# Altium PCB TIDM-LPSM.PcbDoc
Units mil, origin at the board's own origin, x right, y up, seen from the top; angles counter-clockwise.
Board outline 2400 x 1200 mil, 2 copper layers (Top Layer, Bottom Layer), stack 62 mil thick; 16 components, 20 nets, 69 pads, 30 vias.
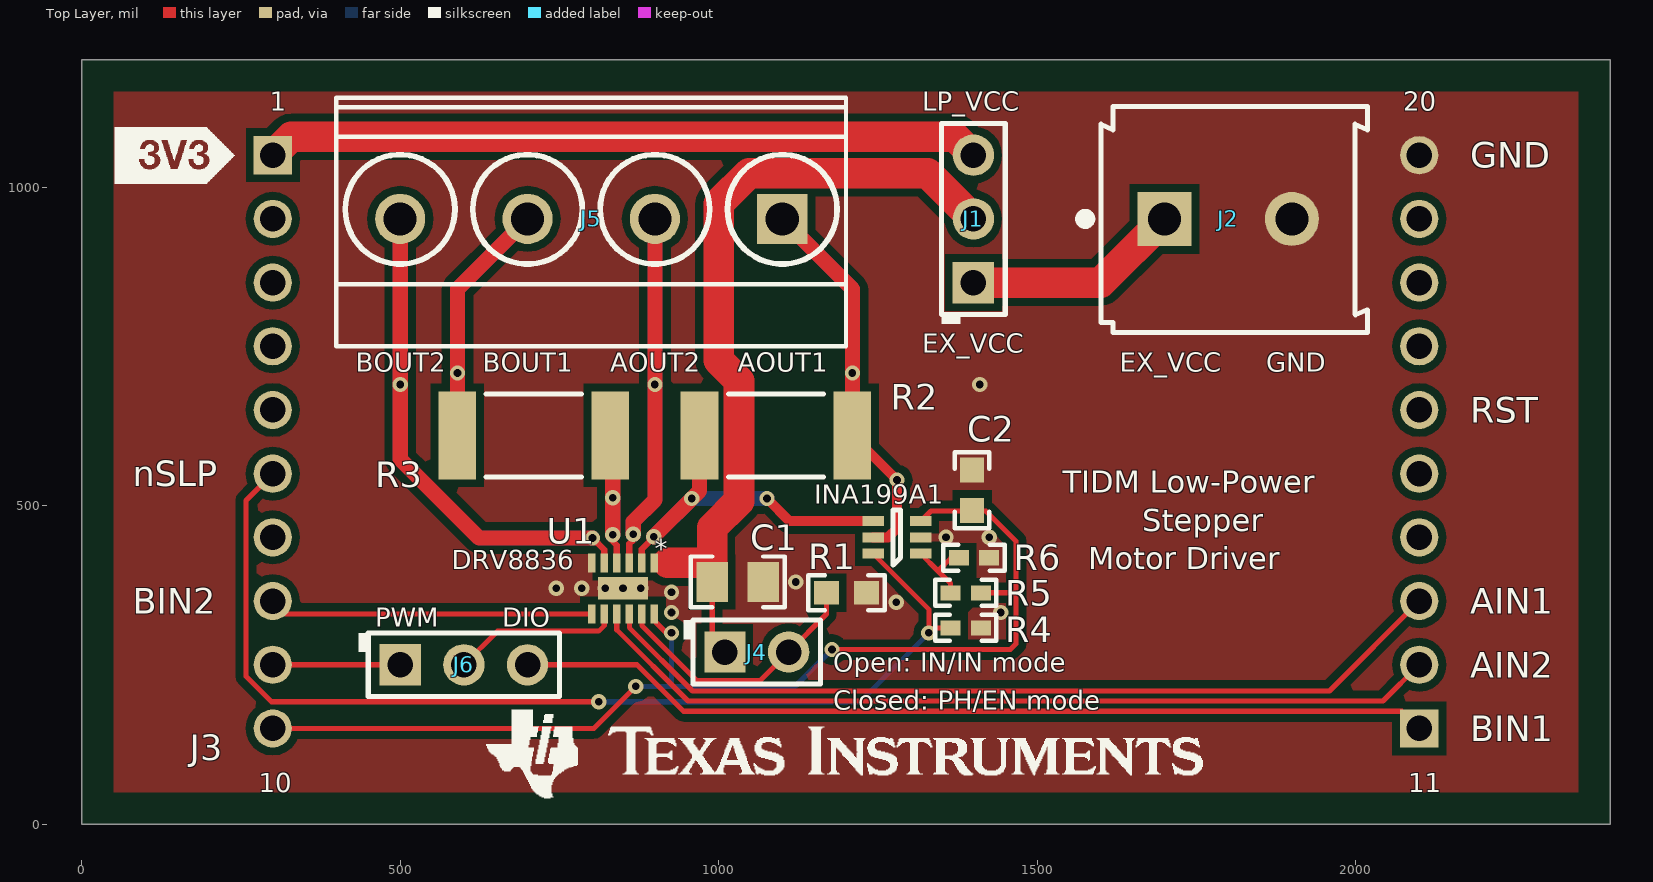
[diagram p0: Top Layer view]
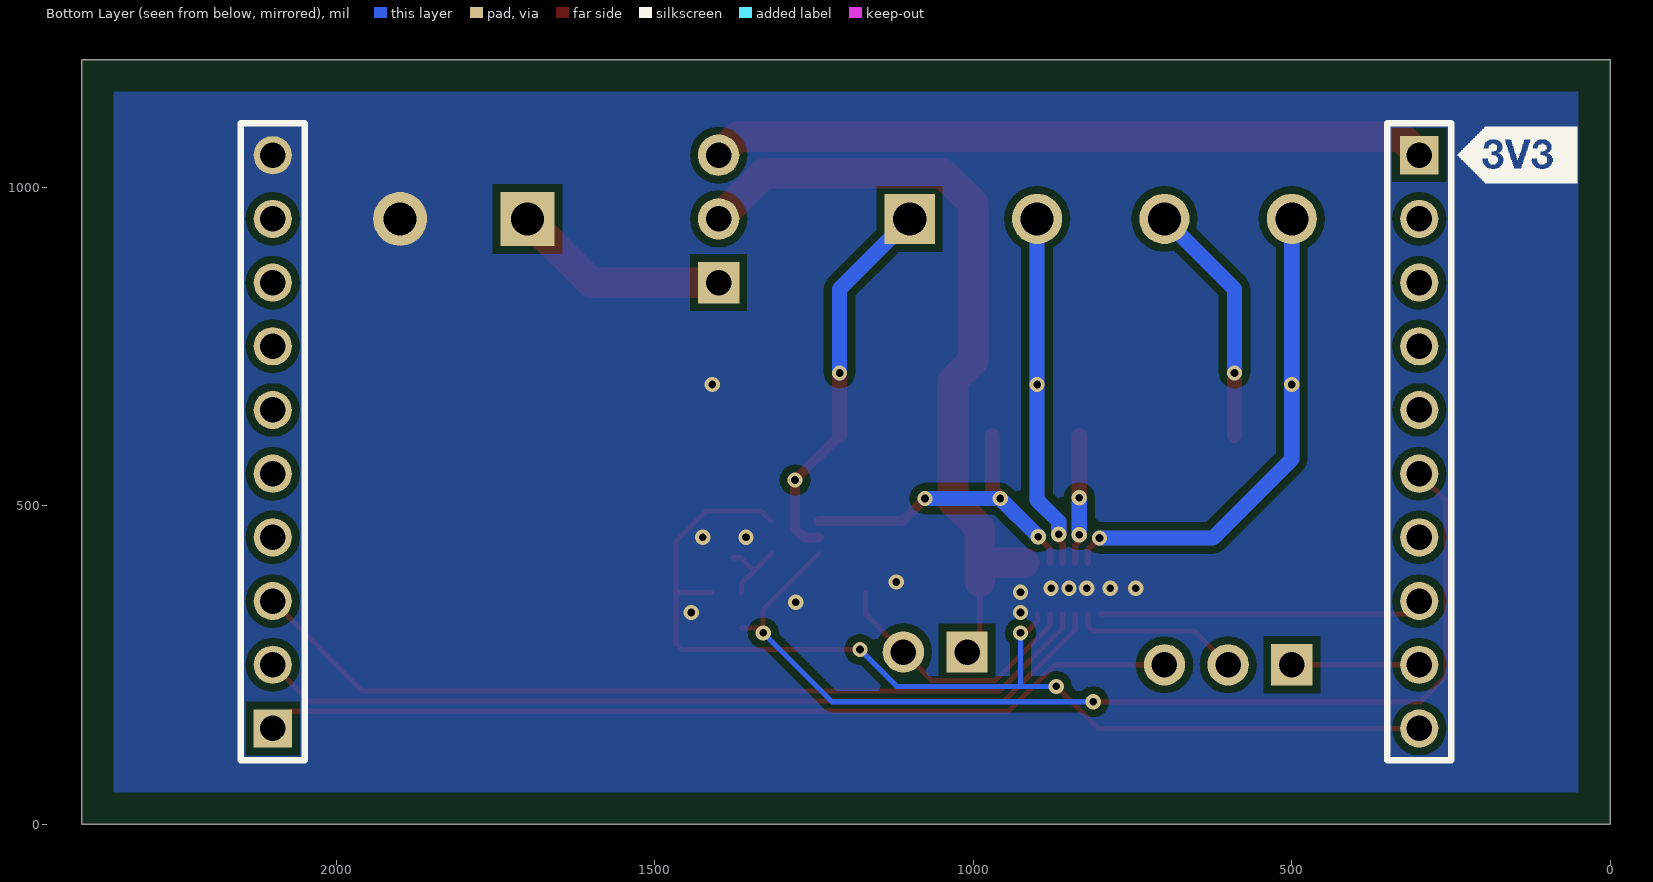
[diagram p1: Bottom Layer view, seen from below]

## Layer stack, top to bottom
Top Layer: signal copper 1.4
Dielectric: core 59.2, FR-4, Dk 4.8
Bottom Layer: signal copper 1.4

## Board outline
0,0 2400,0 2400,1200 0,1200

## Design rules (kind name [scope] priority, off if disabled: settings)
AcuteAngle [All] p1: minimum=4.50000000000000E+0001 checktracksonly=FALSE
AssemblyTestPointUsage [All] p1: valid=2
Clearance Clearance_DRV [InComponent('U1') vs InComponent('U1')] p1: gap=7.5
Clearance Clearance_BoardEdge_MountingHoles [OnCopper and InComponentClass('Mounting Holes') vs IsKeepOut] p2: gap=40
Clearance Clearance_BoardEdge_Poly [OnCopper and InPoly vs IsKeepOut] p3: gap=25
Clearance Clearance_BoardEdge [OnCopper and Not InComponentClass('Logo') and not InComponentClass('FiducialMark') and not InRegion(1000,500,4000,800) and Not IsKeepout vs IsKeepOut] p4: gap=75
Clearance Clearance_Poly [InPolygon] p5: gap=12
Clearance [All] p6: gap=8
ComponentClearance [All] p1: gap=25 collisioncheckmode=3 verticalgap=10 showdistances=FALSE
DiffPairsRouting [All] p1: maxlimit=100 minlimit=10 mostfreqgap=10 maxuncoupledlength=1000
FabricationTestPointUsage TestPointUsage [All] p1: valid=2 allowmultiple=FALSE
FabricationTestpoint Testpoint [All] p1: side=3 testpointundercomponent=TRUE minsize=40 maxsize=100 preferedsize=60 minholesize=0 maxholesize=40 preferedholesize=32 testpointgrid=1 allowsidetop=TRUE allowsidebottom=TRUE usegrid=TRUE gridtolerance=0.01
FanoutControl Fanout_LCC [IsLCC] p1: bgadir=Out bgaviamode=Centered fanoutstyle=Auto fanoutdirection=Alternating viagrid=1 // Fanout_LCC (Default Rule)
FanoutControl Fanout_BGA [IsBGA] p2: bgadir=Out bgaviamode=Centered fanoutstyle=Auto fanoutdirection=Alternating viagrid=1 // Fanout_BGA (Default Rule)
FanoutControl Fanout_Default [All] p4: bgadir=Out bgaviamode=Centered fanoutstyle=Auto fanoutdirection=Alternating viagrid=1 // Fanout_Default (Default Rule)
FanoutControl Fanout_Small [(CompPinCount < 5)] p5: bgadir=Out bgaviamode=Centered fanoutstyle=Auto fanoutdirection=OutThenIn viagrid=1 // Fanout_Small (Default Rule)
HoleSize [All] p1: absolutevalues=TRUE maxlimit=251 minlimit=8 maxpercent=80.000 minpercent=20.000
MinimumAnnularRing MinimumAnnularRing_ThermalPadVias [IsVia and InAnyComponent] p1: minimumring=5.91
MinimumAnnularRing [All] p2: minimumring=9
MinimumSolderMaskSliver MinimumSolderMaskSliver_Logo [InComponentClass('Logo') vs InComponentClass('Logo')] p1: minsoldermaskwidth=0.7
MinimumSolderMaskSliver [All] p2: minsoldermaskwidth=3.94
PlaneConnect [All] p1: planeconnectstyle=Relief reliefexpansion=10 reliefentries=4 reliefconductorwidth=10 reliefairgap=10
PolygonConnect [All] p1: connectstyle=Direct reliefconductorwidth=10 reliefentries=4 polygonreliefangle="90 Angle" airgapwidth=10
RoutingVias ThermalPadVias [IsVia and InAnyComponent] p1: holewidth=7.87 width=19.68 viastyle="Through Hole" minholewidth=7.87 minwidth=19.68 maxholewidth=12.99 maxwidth=23.62
RoutingVias [All] p2: holewidth=16 width=34 viastyle="Through Hole" minholewidth=7.87 minwidth=26 maxholewidth=40 maxwidth=65
SMDToCorner [All] p1: distance=30000
SilkToSilkClearance [All] p1: silktosilkclearance=5
SilkscreenOverComponentPads [All] p1: minsilkscreentomaskgap=5
SolderMaskExpansion [All] p1: expansion=1.97
Width [All] p1: maxlimit=100 minlimit=6 preferedwidth=10 checkconnectedcopper=TRUE
14 further rules are at their usual default settings.

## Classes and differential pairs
component class Header: J1 J4 J6

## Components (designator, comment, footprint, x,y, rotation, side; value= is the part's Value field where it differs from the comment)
C1 "C0805C106K9PAC" 0805_HV 1030,380 r0 top
C2 "0603YC104JAT2A" 0603 1398,524 r90 top
INA199A1 "INA199A1DCK" DCK0006A_N 1280,450 r180 top (schematic designator U2)
J1 "5-146278-3" TE_5-146278-3 1400,950 r90 top
J2 "282841-2" TEC_282841-2 1800,950 r0 top
J3 "Used in BOM report" SSW-110-23-F-S 300,1050 r0 top
J4 "5-146278-2" TE_5-146278-2 1060,270 r0 top
J5 "39544-3004" MOLEX_39544-3004 800,950 r180 top
J6 "5-146278-3" TE_5-146278-3 600,250 r0 top
R1 "CRCW060320K0JNEA" 0603 1201,363 r180 top
R2 "CRA2512-FZ-R010ELF" 2512M 1090,610 r0 top
R3 "CRA2512-FZ-R010ELF" 2512M 710,610 r180 top
R4 "CRCW040210K0JNED" 0402 1388,308 r180 top
R5 "CRCW040210K0JNED" 0402 1388,363 r180 top
R6 "CRCW040210K0JNED" 0402 1401,418 r180 top
U1 "DRV8836DSSR" DSS-12P 850,370 r180 top

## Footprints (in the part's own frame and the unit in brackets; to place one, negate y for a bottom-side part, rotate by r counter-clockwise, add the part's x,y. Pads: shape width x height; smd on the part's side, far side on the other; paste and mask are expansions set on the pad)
0402 [mm] "0402 from SM-752 data"
  rect 0.8x0.6 smd: 1(-0.6,0) 2(0.6,0)
  silkscreen extent -1.22,-0.52 1.22,0.52, body extent -0.55,-0.3 0.55,0.3, height 0.6
0603 [mm] "0603 from SM-752 data"
  rect 1x0.95 smd: 1(-0.8,0) 2(0.8,0)
  silkscreen extent -1.52,-0.69 1.52,0.69, body extent -0.87,-0.47 0.87,0.47, height 0.85
0805_HV [mil] "0805 with 30mil clearance between pads"
  rect 50x63 smd: 1(-40,0) 2(40,0)
  silkscreen extent -74,-40 74,40, body extent -43,-29 43,29, height 43
2512M [mm] "Chip Resistor, Body 6.3x3.2mm, IPC Low Density"
  rect 1.5x3.5 smd: 1(-3.05,0) 2(3.05,0)
  silkscreen extent -1.9,-1.65 1.9,1.65, body extent -3.22,-1.67 3.22,1.67, height 0.71
DCK0006A_N [mm] "SOT23, 6-Leads, Body 2x1.3mm, Pitch 0.65mm, Lead Span 2.1mm, IPC Medium Density"
  rect 0.85x0.4 smd: 1(-0.95,0.65) 2(-0.95,0) 3(-0.95,-0.65) 4(0.95,-0.65) 5(0.95,0) 6(0.95,0.65)
  silkscreen extent -0.15,-1.1 0.15,1.1, body extent -1.14,-1 1.14,1, height 0.94
DSS-12P [mil]
  rect 11.8x30 smd mask+2: 1(-49.2,-40) 2(-29.5,-40) 3(-9.8,-40) 4(9.9,-40) 5(29.6,-40) 6(49.3,-40) 7(49.3,40) 8(29.6,40) 9(9.9,40) 10(-9.8,40) 11(-29.5,40) 12(-49.2,40)
  rect 79x35 smd: 13(0,0)
MOLEX_39544-3004 [mm] "Molex"
  rect 2x2 hole 1.321: 1(-7.62,0)
  round 2 hole 1.321: 2(-2.54,0) 3(2.54,0) 4(7.62,0)
  silkscreen extent -10.16,-4.83 10.16,5.08, body extent -10.16,-4.83 10.16,5.08, height 14.49
SSW-110-23-F-S [mil]
  rect 60x60 hole 40: 1(0,0) 11(1800,-900)
  round 60 hole 40: 2(0,-100) 3(0,-200) 4(0,-300) 5(0,-400) 6(0,-500) 7(0,-600) 8(0,-700) 9(0,-800) 10(0,-900) 12(1800,-800) 13(1800,-700) 14(1800,-600) 15(1800,-500) 16(1800,-400) 17(1800,-300) 18(1800,-200) 19(1800,-100) 20(1800,0)
  silkscreen extent -248,-44 -60,44, body extent -50,-950 1850,50, height 335
TE_5-146278-2 [mm] "TE CONNECTIVITY"
  rect 1.65x1.65 hole 1.016: 1(-1.27,0)
  round 1.65 hole 1.016: 2(1.27,0)
  silkscreen extent -2.92,-1.27 2.54,1.27, body extent -2.41,-1.17 2.41,1.17, height 8.13
TE_5-146278-3 [mm] "TE CONNECTIVITY"
  rect 1.65x1.65 hole 1.016: 1(-2.54,0)
  round 1.65 hole 1.016: 2(0,0) 3(2.54,0)
  silkscreen extent -4.19,-1.27 3.81,1.27, body extent -3.68,-1.17 3.68,1.17, height 8.13
TEC_282841-2 [mm] "TE Connectivity"
  rect 2.15x2.15 hole 1.321: 1(-2.54,0)
  round 2.15 hole 1.321: 2(2.54,0)
  silkscreen extent -5.9,-4.52 5.55,4.47, body extent -5.08,-4.52 5.58,4.48, height 15.2

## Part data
C1: "CAP, CERM, 10uF, 6.3V, +/-10%, X5R, 0805"
C2: "CAP, CERM, 0.1uF, 16V, +/-5%, X7R, 0603"
INA199A1: "Voltage Output, High or Low Side Measurement, Bi-Directional Zerø-Drift Series Current-Shunt Monitor, DCK0006A"
J1 J6: "Header, 100mil, 3x1, Tin, TH"
J2: "Terminal Block, 2x1, 5.08mm, TH"
J3: library part "MSP-EXP430FR5969 2x10 Header"
J4: "Header, 100mil, 2x1, Tin, TH"
J5: "Terminal Block, 4x1, 5.08mm, TH"
R1: "RES, 20k ohm, 5%, 0.1W, 0603"
R2 R3: "RES, 0.01 ohm, 1%, 3W, 2512"
R4 R5 R6: "RES, 10k ohm, 5%, 0.063W, 0402"
U1: library part DRV8835DSSR, "IC, DUAL LOW VOLTAGE H-BRIDGE"

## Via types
v1: diameter 24, hole 12, Top Layer to Bottom Layer, 30 vias

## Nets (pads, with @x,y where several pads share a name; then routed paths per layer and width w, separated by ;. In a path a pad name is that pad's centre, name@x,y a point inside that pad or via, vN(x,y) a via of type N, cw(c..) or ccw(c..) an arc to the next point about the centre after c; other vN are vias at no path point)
BIN1: J6.2 U1.8 | length 264.4
  Top Layer w8: J6.2 652.72,302.72 811.72,302.72 820.4,311.4 U1.8
EX_VCC: J1.1 J2.1 | length 341.4
  Top Layer w48: J1.1 1600,850 J2.1
GND: C1.2 C2.2 INA199A1.2 J2.2 J3.20 R1.1 R4.1 R6.1 U1.6 U1.13
  other v1: 926,332 1443,331.99 1279,348 926,364 745,370 785,370 822,370 850,370 878,370 1121,380 1357,450 1425,450 1410,690
IN+: INA199A1.4 R2.1 U1.2 | length 620.6
  Top Layer w10: U1.2 879.5,431.5 v1@898,450
  Top Layer w16: v1(1076,511) 1111.41,475.59 INA199A1.4
  Top Layer w24: v1(898,451) 970,523 970,609.92 R2.1
  Bottom Layer w24: v1(898,451) v1(958,511) v1(1076,511)
IN-: INA199A1.5 J5.1 R2.2 | length 891.4
  Top Layer w16: R2.2 v1(1280,540.08) 1280,464 1266,450 INA199A1.5
  Top Layer w24: J5.1 1210.08,839.92 v1(1210.08,708) R2.2
  Bottom Layer w24: J5.1 1210.08,839.92 v1(1210.08,708)
NetJ1_3: J1.3 J3.1 | length 1124.2
  Top Layer w48: J3.1 329.15,1079.16 1370.84,1079.16 J1.3
NetJ4_2: J4.2 R1.2 U1.11 | length 421.1
  Top Layer w8: U1.11 879.5,311.5 966,225 1065,225 J4.2 1169.5,329.51 R1.2
NetJ5_2: J5.2 U1.3 | length 1065.7
  Top Layer w10: U1.3 859.8,439.8 866,446 v1(866,455)
  Top Layer w24: v1(866,455) 866,475 900,509 J5.2
  Bottom Layer w24: v1(866,455) 866,475 900,509 J5.2
  other v1: 900,690
NetJ5_3: J5.3 R3.2 | length 673.2
  Top Layer w24: R3.2 589.92,839.92 J5.3
  Bottom Layer w24: v1(590,708) 590,840 J5.3
NetJ5_4: J5.4 U1.5 | length 1507.3
  Top Layer w10: v1(802,449) 820.4,430.6 U1.5
  Top Layer w24: J5.4 500,573 624,449 v1(802,449)
  Bottom Layer w24: J5.4 500,573 624,449 v1(802,449)
  other v1: 500,690
NetR3_1: R3.1 U1.4 | length 260.5
  Top Layer w10: v1(834,454) 834,444 840.1,437.9 U1.4
  Top Layer w24: v1(834,454) v1(834,512) R3.1@834,610
  Bottom Layer w24: v1(834,454) v1(834,512)
NetR5_2: INA199A1.1 R5.2 R6.2 | length 122.3
  Top Layer w8: INA199A1.1 1344.47,397.34 ; R5.2 1364.38,377.43 1344.47,397.34 ; R6.2 1365.13,418 1344.47,397.34
P1.3/BIN1: J3.11 J6.3 | length 1441.4
  Top Layer w8: J6.3 872,250 945,177 2073,177 J3.11
P1.4/AIN2: J3.12 U1.9 | length 1355
  Top Layer w8: U1.9 840.1,304.9 952,193 2043,193 J3.12
P1.5/AIN1: J3.13 U1.10 | length 1361.5
  Top Layer w8: U1.10 859.8,308.2 959,209 1959,209 J3.13
P2.4/OUT: INA199A1.6 J3.6 R4.2 | length 1670
  Top Layer w8: J3.6 258,508 258,232 298,192 v1(812,192) ; INA199A1.6 1330,337.01 v1(1330,300) 1338,308 R4.2
  Bottom Layer w8: v1@809,192 1222,192 v1(1330,300)
P3.4/BIN2: J3.8 U1.7 | length 509
  Top Layer w8: J3.8 320,330 U1.7
P3.5/BIN1: J3.9 J6.1 | length 200
  Top Layer w8: J3.9 J6.1
P3.6/NSLEEP/V+: C2.1 INA199A1.3 J3.10 R5.1 U1.12 | length 1744.1
  Top Layer w8: J3.10 804,150 v1(870,216) ; U1.12 899.2,318.8 918,300 v1(926,300) ; v1(1178,274) 1458,274 1467,283 1467,363 ; INA199A1.3 1333.31,491.5 1419.5,491.5 1467,444 1467,363 ; R5.1 1467,363
  Bottom Layer w8: v1(870,216) 926,216 ; v1(926,300) 926,216 ; v1(1178,274) 1120,216 926,216
VCC: C1.1 J1.2 J4.1 U1.1 | length 1273.4
  Top Layer w8: U1.1 920,410 ; C1.1 990,290 J4.1
  Top Layer w48: 920,410 C1.1@980,410 ; C1.1 990,465 1032,507 1032,696 1000,728 1000,974 1048,1022 1328,1022 J1.2
pads on no net: J3.2 J3.3 J3.4 J3.5 J3.7 J3.14 J3.15 J3.16 J3.17 J3.18 J3.19

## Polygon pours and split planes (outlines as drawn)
GND on Top Layer "Top Layer-GND" (solid, remove dead copper, pour order 4): 50,50 2350,50 2350,1150 50,1150
GND on Bottom Layer "Bottom Layer-GND" (solid, remove dead copper, pour order 3): 50,50 2350,50 2350,1150 50,1150

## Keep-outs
Keep-Out Layer:
  lines w10: -5,3450 cw(c0,3450) 0,3455 ; -5,3450 cw(c0,3450) 0,3455 ; -5,3450 cw(c0,3450) 0,3455 ; -5,3450 cw(c0,3450) 0,3455 ; -5,3450 cw(c0,3450) 0,3455 ; -5,3450 cw(c0,3450) 0,3455 ; 4950,-5 ccw(c4950,0) 4955,0 ; 4950,-5 ccw(c4950,0) 4955,0 ; 4950,-5 ccw(c4950,0) 4955,0 ; 4950,-5 ccw(c4950,0) 4955,0 ; 4950,-5 ccw(c4950,0) 4955,0 ; 4950,-5 ccw(c4950,0) 4955,0 ; 4950,3455 cw(c4950,3450) 4955,3450 ; 4950,3455 cw(c4950,3450) 4955,3450 ; 4950,3455 cw(c4950,3450) 4955,3450 ; 4950,3455 cw(c4950,3450) 4955,3450 ; 4950,3455 cw(c4950,3450) 4955,3450 ; 4950,3455 cw(c4950,3450) 4955,3450
  text ".Layer_Name" at 577,-858.49 h60

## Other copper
Top Layer:
  text ".Layer_Name" at 577,-858.49 h60
Bottom Layer:
  text ".Layer_Name" at 577,-858.49 h60

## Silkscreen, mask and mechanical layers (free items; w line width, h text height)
Top Overlay:
  drawing of 1249 lines, arcs and shapes, not listed
  text "LP_VCC" at 1320,1120 h30
  text "EX_VCC" at 1320,740 h30
  text "BOUT2" at 430,710 h30
  text "BOUT1" at 630,710 h30
  text "AOUT2" at 830,710 h30
  text "AOUT1" at 1030,710 h30
  text "EX_VCC" at 1630,710 h30
  text "GND" at 1860,710 h30
  text "nSLP" at 80,530 h40
  text "TIDM Low-Power" at 1540,520 h35
  text "Stepper" at 1665,460 h35
  text "DRV8836" at 581,400 h30
  text "Motor Driver" at 1580,400 h35
  text "BIN2" at 80,330 h40
  text "AIN1" at 2180,330 h40
  text "PWM" at 461,310 h30
  text "DIO" at 660,310 h30
  text "Open: IN/IN mode" at 1180,239 h30
  text "AIN2" at 2180,230 h40
  text "Closed: PH/EN mode" at 1180,179 h30
  text "BIN1" at 2180,130 h40
  text ".Layer_Name" at 577,-858.49 h60
Bottom Overlay:
  text ".Layer_Name" at 577,-858.49 h60
Top Paste:
  text ".Layer_Name" at 577,-858.49 h60
Bottom Paste:
  text ".Layer_Name" at 577,-858.49 h60
Top Solder:
  text ".Layer_Name" at 577,-858.49 h60
  text ".Layer_Name" at 577,-858.49 h60
Bottom Solder:
  text ".Layer_Name" at 577,-858.49 h60
Drill Guide:
  text ".Layer_Name" at 577,-858.49 h60
M1 Board Outline:
  the board outline again, w10
  text ".Layer_Name" at 577,-858.49 h60
M2 Board Dimensions:
  rectangle: -0.5,-285.5 124.5,-160.5
  rectangle: 124.5,-410.5 499.5,-285.5
  lines w7: -0.5,-285.5 999.5,-285.5 ; 124.5,-410.5 124.5,-160.5 ; 249.5,-410.5 249.5,-160.5 ; 499.5,-410.5 499.5,-160.5 ; 749.5,-410.5 749.5,-160.5 ; -0.5,-410.5 999.5,-410.5 999.5,-160.5 -0.5,-160.5 -0.5,-410.5
  lines w10: -0.5,-475.5 -0.5,-455.5 ; 59.5,-485.5 -0.5,-465.5 ; 59.5,-445.5 -0.5,-465.5 ; 223.58,-465.5 -0.5,-465.5 ; 775.42,-465.5 999.5,-465.5 ; 939.5,-485.5 999.5,-465.5 ; 939.5,-445.5 999.5,-465.5 ; 999.5,-475.5 999.5,-455.5
  text "1000 (mil)" at 233.58,-501.49 h60
  text ".Layer_Name" at 577,-858.49 h60
M3 3D STEP Top:
  text ".Layer_Name" at 577,-858.49 h60
M4 3D STEP Bottom:
  text ".Layer_Name" at 577,-858.49 h60
M5 Assembly Top:
  lines w10: -292,-930.17 6308,-930.17 ; -292,-726.83 6310,-726.83 ; -292,-523.5 -292,-1133.5 3713,-1133.5 6310,-1133.5 6310,-523.5 -291.5,-523.5 -291.5,-1133.5 1284,-1133.5 ; 2173,-1133.5 2173,-523.5 ; 3440,-726.83 3440,-523.5 ; 4280,-726.83 4280,-523.5 ; 4902,-1140 4902,-937.17
  text "COMPONENTS MARKED 'DNP' SHOULD NOT BE POPULATED." at 1153.5,-318.5 h60
  text "ASSEMBLY VARIANT:" at 1153,-434 h60
  text ".VariantName" at 2189,-434 h60
  text "PCB VIEWED FROM TOP SIDE" at -228.5,-655.67 h60
  text "BOARD #:" at 2248,-655.67 h60
  text ".PRJ_Number" at 2793.5,-655.67 h60
  text "REV:" at 3638,-655.67 h60
  text ".PCB_Rev" at 3929.5,-655.67 h60
  text "SVN REV:" at 4476,-655.67 h60
  text ".VersionControl_RevNumber" at 4982,-655.67 h60
  text "IGNORE ->" at -228.5,-858.49 h60
  text "PLOT NAME =" at -228.5,-1064.34 h60
  text ".plot_File_Name" at 577,-1064.34 h60
  text "GENERATED    :" at 2250,-1064.34 h60
  text ".Print_Date" at 3119.5,-1064.34 h60
  text ".Print_Time" at 3848.5,-1064.34 h60
  text "TEXAS INSTRUMENTS" at 5113,-1064.34 h60
M6 Assembly Bottom:
  lines w10: -292.5,-727.33 6309.5,-727.33 ; -290.5,-930.67 6309.5,-930.67 ; 1115.5,-1140.5 1115.5,-937.67 ; 1737.5,-727.33 1737.5,-524 ; 2577.5,-727.33 2577.5,-524 ; 3844.5,-1134 3844.5,-524 ; 4733.5,-1134 6309,-1134 6309,-524 -292.5,-524 -292.5,-1134 2304.5,-1134 6309.5,-1134 6309.5,-524
  text "COMPONENTS MARKED 'DNP' SHOULD NOT BE POPULATED." at 6102,-318 h60
  text ".VariantName" at 5058,-434 h60
  text "ASSEMBLY VARIANT:" at 6097,-434 h60
  text ".VersionControl_RevNumber" at 1035.5,-656.17 h60
  text "SVN REV:" at 1541.5,-656.17 h60
  text ".PCB_Rev" at 2088,-656.17 h60
  text "REV:" at 2379.5,-656.17 h60
  text ".PRJ_Number" at 3224,-656.17 h60
  text "BOARD #:" at 3769.5,-656.17 h60
  text "PCB VIEWED FROM BOTTOM SIDE" at 6246,-656.17 h60
  text "IGNORE ->" at 2547.85,-858.49 h60
  text "TEXAS INSTRUMENTS" at 904.5,-1064.84 h60
  text ".Print_Time" at 2169,-1064.84 h60
  text ".Print_Date" at 2898,-1064.84 h60
  text "GENERATED    :" at 3767.5,-1064.84 h60
  text ".plot_File_Name" at 5440.5,-1064.84 h60
  text "PLOT NAME =" at 6246,-1064.84 h60
M9 Title Sheet:
  drawing of 57 lines, arcs and shapes, not listed
  text "1" at 739.84,8036.5 h70
  text "2" at 3235.5,8036.5 h70
  text "3" at 5724.84,8036.5 h70
  text "4" at 8231.51,8036.5 h70
  text "5" at 10730.5,8036.5 h70
  text "6" at 13235.5,8036.5 h70
  text "A" at -416.5,6893.5 h70
  text "A" at 14383.5,6893.5 h70
  text "B" at -416.5,4513.5 h70
  text "B" at 14383.5,4513.5 h70
  text "C" at -416.5,2138.5 h70
  text "C" at 14383.5,2138.5 h70
  text "PROJECT TITLE:" at 11343.5,277.5 h45
  text ".PRJ_Title" at 11393.5,144.17 h70
  text "DESIGNED FOR:" at 11343.5,-23.5 h45
  text ".PRJ_Customer" at 11393.5,-163.5 h70
  text "D" at -416.5,-231.5 h70
  text "D" at 14383.5,-231.5 h70
  text "FILE NAME:" at 11343.5,-323.5 h45
  text ".PCB_File_Name_No_Path" at 11393.5,-443.5 h70
  text "Texas Instruments (TI) and/or its licensors do not warrant the accuracy or completeness of this specification" at 6374,-605.34 h45
  text "ENGINEER:" at 11343.5,-613.5 h45
  text "LAYOUT BY:" at 12848.5,-613.5 h45
  text "or any information contained therein. TI and/or its licensors do not warrant that this design will meet" at 6329.01,-718 h45
  text ".PRJ_Engineer" at 11393.5,-768.49 h70
  text ".PCB_Layout" at 12899,-768.49 h70
  text "the specifications, will be suitable for your application or fit for any particular purpose, or will operate in" at 6329.01,-830.67 h45
  text ".Layer_Name" at 577,-858.49 h60
  text "ALTIUM DESIGNER VERSION:" at 12848.5,-923.5 h45
  text "an implementation. TI and/or its licensors do not warrant that the design is production worthy. You should" at 6329.01,-943.33 h45
  text "completely validate and test your design implementation to confirm the system functionality for your application." at 6374,-1056 h45
  text ".print_Scale" at 11393.5,-1056.83 h70
  text ".Application_BuildNumber" at 12899,-1056.83 h70
  text "1" at 739.84,-1263.5 h70
  text "2" at 3235.5,-1263.5 h70
  text "3" at 5724.84,-1263.5 h70
  text "4" at 8231.51,-1263.5 h70
  text "5" at 10730.5,-1263.5 h70
  text "6" at 13235.5,-1263.5 h70
M10 Fab Notes:
  drawing of 212 lines, arcs and shapes, not listed
  text "DESIGN INFORMATION" at 12381.02,6810 h60
  text "(REFER ALSO ARRAY/PANEL PROFILING INFORMATION)" at 12019.46,6648.29 h60
  text "BOARD SIZE" at 11333.46,6644 h60
  text "1200MIL" at 11795.78,6516.18 h60
  text "X" at 12301.46,6516.18 h60
  text "2400MIL" at 12532.78,6516.18 h60
  text "Number of Layers :" at 11736.46,6319 h60
  text "2" at 12831.27,6309 h60
  text "MIN. TRACK WIDTH:" at 11736.46,6180 h60
  text "8" at 12832.7,6180 h60
  text "MIL" at 12987.46,6180 h60
  text "MIN. CLEARANCE:" at 11736.46,6048 h60
  text "8" at 12832.7,6048 h60
  text "MIL" at 12987.46,6048 h60
  text "MIN. VIA PAD SIZE:" at 11736.46,5916 h60
  text "24" at 12802.71,5916 h60
  text "MIL" at 12987.46,5916 h60
  text "0.05mm (2MIL)" at 12431.46,5774.29 h60
  text "MINIMUM ANNULAR RING" at 11407.23,5770 h60
  text "EXTERNAL" at 13139.46,5770 h60
  text "PER" at 11607.23,5652 h60
  text "IPC-D-275 CLASS 2 LEVEL C" at 11827.23,5652 h60
  text "MIL, HOLES" at 13315.46,5539.71 h60
  text "+/-" at 12923,5539 h60
  text "+/-" at 13777,5539 h60
  text "REGISTRATION TOLERANCES:" at 11407.23,5534 h60
  text "METAL" at 12607,5534 h60
  text "5" at 13183.2,5534 h60
  text "3" at 14016.2,5534 h60
  text "MIL" at 14132.46,5534 h60
  text "MATERIAL:" at 11332.46,5324.54 h60
  text "FR-4 High Tg" at 12318.9,5184.21 h60
  text "FR-408" at 11753.46,5175.64 h60
  text "X" at 12165.46,5175.64 h60
  text "OTHER" at 13241.46,5175.64 h60
  text "62 MIL (1.6mm) +/-10%" at 12073.56,5012.92 h60
  text "THICKNESS:" at 11407.23,5008.64 h60
  text "X" at 11945.4,5008.64 h60
  text "OTHER" at 13358.46,5008.64 h60
  text "TOLERANCE:" at 11407.23,4850.64 h60
  text "X" at 12246.53,4850.64 h60
  text "ANSI IPC-6012 TYPE 3 CLASS 2" at 12433.48,4850.64 h60
  text "OTHER +/-" at 12433.46,4694.64 h60
  text "BOW & TWIST:" at 11407.23,4537.64 h60
  text "X" at 12246.53,4537.64 h60
  text "ANSI IPC-6012 TYPE 3 CLASS 2" at 12433.48,4537.64 h60
  text "OTHER +/-" at 12433.46,4379.13 h60
  text "COPPER THICKNESS (FINISHED):" at 11332.46,4243.64 h60
  text "1.4MIL (1oz)" at 12212.46,4090.92 h60
  text "2MIL (1.4oz)" at 12979.46,4090.92 h60
  text "2.8MIL (2oz)" at 13706.46,4090.92 h60
  text "OUTER:" at 11689.46,4086.64 h60
  text "X" at 12084,4086 h60
  text "1.4MIL (1oz)" at 12212.46,3933.92 h60
  text "2.8MIL (2oz)" at 12979.46,3933.92 h60
  text "N/A" at 13706,3934.29 h60
  text "INNER SIGNAL:" at 11400.38,3929.64 h60
  text "X" at 13581,3929 h60
  text "DRILLING:" at 11332.46,3790.64 h60
  text "REFERENCE:" at 11407.23,3673.64 h60
  text "X" at 12055.46,3673.64 h60
  text "AS SHOWN" at 12242.46,3673.64 h60
  text "X" at 12956.46,3673.64 h60
  text "NC_DRILL FILES" at 13093.46,3673.64 h60
  text "PTH MIN COPPER THICKNESS:" at 11407.23,3515.64 h60
  text "X" at 12757.46,3515.64 h60
  text "1MIL" at 12894.46,3515.64 h60
  text "OTHER" at 13391.46,3515.64 h60
  text "BOARD FINISH:" at 11332.46,3356.64 h60
  text "SILKSCREEN:" at 11487.68,3238.64 h60
  text "X" at 12436.46,3238.64 h60
  text "TOP" at 12562.46,3238.64 h60
  text "BOTTOM" at 13073.46,3238.64 h60
  text "X" at 12435,3077 h60
  text "SILKSCREEN COLOR:" at 11487.68,3071.64 h60
  text "WHITE" at 12562.46,3071.64 h60
  text "OTHER" at 13073.46,3071.64 h60
  text "SOLDER RESIST COLOR:" at 11487.68,2901.64 h60
  text "X" at 13155,2745 h60
  text "RED" at 13654,2745 h60
  text "GREEN" at 12182.46,2742.44 h60
  text "BLUE" at 12773.46,2742.44 h60
  text "OTHER" at 13311.46,2742.44 h60
  text "IMMERSION GOLD (ENIG)" at 12393.46,2553.92 h60
  text "ENEPIG" at 13731,2550.64 h60
  text "SURFACE FINISH:" at 11332.46,2549.64 h60
  text "X" at 12206.51,2549.64 h60
  text "IMM. TIN/SILVER OR EQUIV" at 11662,2392.64 h60
  text "OTHER" at 13093.46,2392.64 h60
  text "ARRAY/PANEL:" at 11332.46,2213.64 h60
  text "CUT AND TRIM PER MECH LAYER 1" at 12393.46,2209.35 h60
  text "N.C. ROUTE" at 12393.46,2057.64 h60
  text "V. SCORE" at 13259.46,2057.64 h60
  text "CERTIFICATION:" at 11332.46,1920.64 h60
  text "MATERIALS AND WORKMANSHIP FOR ALL PCBS" at 12057.46,1920.64 h60
  text "TO MEET OR EXCEED THE REQUIREMENTS OF:" at 12057.46,1822.64 h60
  text "X" at 11683.96,1686.13 h60
  text "ANSI IPC-A-600F CLASS ->" at 11822.96,1686.13 h60
  text "X" at 13462.02,1686.13 h60
  text "2" at 13580.96,1686.14 h60
  text "1" at 13265.96,1684.64 h60
  text "3" at 13934.96,1684.64 h60
  text "X" at 11686.02,1526.64 h60
  text "UL 94V-0" at 11822.96,1526.64 h60
  text "X" at 12498.02,1526.64 h60
  text "RoHS" at 12634.96,1526.64 h60
  text "OTHER" at 13279.36,1526.64 h60
  text "PER ORDER" at 13676.42,1526.64 h60
  text "ADDITIONAL REQUIREMENTS:" at 11332.46,1385.64 h60
  text "MICROSECTION:" at 11407.23,1270.64 h60
  text "YES" at 12312.96,1270.64 h60
  text "REQUIRED" at 13174.46,1114.49 h60
  text "BARE BOARD ELEC. TEST:" at 11407.23,1111.64 h60
  text "NONE" at 12712.96,1111.64 h60
  text "X" at 13047.46,1111.64 h60
  text "PER ORDER" at 13766.46,1111.64 h60
  text "MANUFACTURER'S UL:" at 11407.23,954.64 h60
  text "RAIL" at 12572.96,950.35 h60
  text "METAL" at 13064.77,950.35 h60
  text "X" at 13440,950 h60
  text "SILK" at 13576.46,950.35 h60
  text ".Layer_Name" at 577,-858.49 h60
M11 Gerber Information:
  lines w10: -292,-930.17 6308,-930.17 ; -292,-726.83 6310,-726.83 ; -292,-523.5 -292,-1133.5 3713,-1133.5 6310,-1133.5 6310,-523.5 -291.5,-523.5 -291.5,-1133.5 1284,-1133.5 ; 2173,-1133.5 2173,-523.5 ; 3440,-726.83 3440,-523.5 ; 4280,-726.83 4280,-523.5 ; 4902,-1140 4902,-937.17
  text "ALL ARTWORK VIEWED FROM TOP SIDE" at -228.5,-655.67 h60
  text "BOARD #:" at 2248,-655.67 h60
  text ".PRJ_Number" at 2793.5,-655.67 h60
  text "REV:" at 3638,-655.67 h60
  text ".PCB_Rev" at 3929.5,-655.67 h60
  text "SVN REV:" at 4476,-655.67 h60
  text ".VersionControl_RevNumber" at 4982,-655.67 h60
  text "LAYER NAME =" at -228.5,-858.49 h60
  text "PLOT NAME =" at -228.5,-1064.34 h60
  text ".plot_File_Name" at 577,-1064.34 h60
  text "GENERATED    :" at 2250,-1064.34 h60
  text ".Print_Date" at 3119.5,-1064.34 h60
  text ".Print_Time" at 3848.5,-1064.34 h60
  text "TEXAS INSTRUMENTS" at 5113,-1064.34 h60
M12 Stackup:
  lines w6: 11360,7460 13910,7460 ; 11360,7564.4 13910,7564.4 ; 11300,6975 ccw(c11334,6975) 11334,6941 13936,6941 ccw(c13936,6975) 13970,6975 13970,7681 ccw(c13936,7681) 13936,7715 11334,7715 ccw(c11334,7681) 11300,7681 11300,6975
  text "The Stackup Legend below this is static." at 11605.5,7874.5 h60
  text "If you change the stackup, update the Legend." at 11615.5,7784.5 h60
  text "Layer Stack Up Detail for: Ref_Design.PcbDoc" at 11360,7597.1 h57
  text "Layer" at 11360,7525.4 h24
  text "Gerber" at 12255.81,7525.4 h24
  text "Copper" at 12819.33,7525.4 h24
  text "Dielectric" at 13422.04,7525.4 h24
  text "Name" at 11360,7477.4 h24
  text "Document" at 12255.81,7477.4 h24
  text "Thickness" at 12819.33,7477.4 h24
  text "Material" at 13422.04,7477.4 h24
  text "Top Solder Mask" at 11360,7384.44 h34
  text "(.GTS)" at 12255.81,7384.44 h34
  text "Solder Resist" at 13422.04,7384.44 h34
  text "Top Layer" at 11360,7287.69 h34
  text "(.GTL)" at 12255.81,7287.69 h34
  text "1.4mil" at 12819.33,7287.69 h34
  text "FR-4" at 13422.04,7239.31 h34
  text "Bottom Layer" at 11360,7190.94 h34
  text "(.GBL)" at 12255.81,7190.94 h34
  text "1.4mil" at 12819.33,7190.94 h34
  text "Bottom Solder Mask" at 11360,7094.19 h34
  text "(.GBS)" at 12255.81,7094.19 h34
  text "Solder Resist" at 13422.04,7094.19 h34
  text ".Layer_Name" at 577,-858.49 h60
M13 Component Bodies Top:
  text ".Layer_Name" at 577,-858.49 h60
M14 Component Bodies Bottom:
  text ".Layer_Name" at 577,-858.49 h60
M15 Courtyards Top:
  text ".Layer_Name" at 577,-858.49 h60
M16 Courtyards Bottom:
  text ".Layer_Name" at 577,-858.49 h60
Drill Drawing:
  text ".legend" at 5122.5,725.5 h60
  text "Drill Table" at 5147.5,540.5 h60
  text ".Layer_Name" at 577,-858.49 h60

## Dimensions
0,0 to 0,1200 on M2 Board Dimensions
0,0 to 2400,0 on M2 Board Dimensions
